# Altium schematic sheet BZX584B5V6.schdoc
size 127 x 101 mm
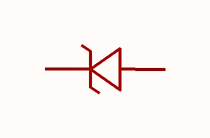
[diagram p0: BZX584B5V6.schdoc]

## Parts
D?  bzx584b5v6  [SOD-523_L1.2-W0.8-LS1.6-FD]  (value not drawn)

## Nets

Not connected (* = marked no-connect by the designer): D? 1(A) 2(K)

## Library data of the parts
D? = bzx584b5v6: 二极管配置:1个独立式;稳压值(标称值):5.6V;稳压值(范围值):5.49V~5.71V;耗散功率(Pd):150mW;; Manufacturer: CJ(江苏长电/长晶); AddInBom: yes; ModelId: 8f56a03db567494d8f4c9d12aa52a741; ModelName: SOD-523_L1.2-W0.8-H0.7-LS1.6; ModelTransform: 62.992,31.496,0,0,0,0,0,0,0; Diode Configuration: 1个独立式; Zener Voltage(Nom): 5.6V; Reverse Leakage Current (Ir): 1uA; Pd - Power Dissipation: 150mW; Impedance(Zzt): 40Ω; Impedance(Zzk): 400Ω; Operating Junction Temperature Range: -55℃~+150℃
